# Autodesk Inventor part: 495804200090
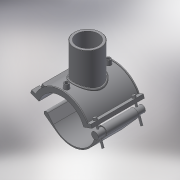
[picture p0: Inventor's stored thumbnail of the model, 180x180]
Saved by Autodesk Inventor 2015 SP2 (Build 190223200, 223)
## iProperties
Created: 2017-07
Part Number: 495804200090
Material: Generic
Description: PLASSON BRANCH SADDLE 200-90
Document SubType Name: Modeling
Designer: KIM
Density: 1 g/cm^3
Appearance: Default
Author: KIM
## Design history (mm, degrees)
derived "495804.ipt"
feature "Solid1::495804.ipt"
feature "Solid2::495804.ipt"
tag "TaggingFeature1"
body "Solid1"
body "Solid2"
other parameters: "d2" = 262.6, "d4" = 176, "d5" = 0, "d6" = 0.1, "d8" = 0, "d19" = 6, "d20" = 6, "d21" = 105.6, "d23" = 0, "d24" = 52.8, "d26" = 0, "d27" = 3, "d28" = 3, "d29" = 3, "d30" = 66.66667, "d31" = 6, "d32" = 0, "d33" = 0, "d34" = 0.6, "d40" = 119.6, "d41" = 99, "d43" = 0, "d45" = 0, "d50" = 0, "d70" = 15, "d72" = 0, "d73" = 6, "d75" = 5, "d76" = 0, "d79" = 15, "d80" = 70.4, "d82" = 5 deg, "d84" = 4, "d85" = 14, "d86" = 0, "d87" = 3, "d88" = 0, "d89" = 1, "d90" = 1, "d91" = 140.8, "d92" = 0, "d93" = 0.5, "d94" = 105.26316, "d96" = 234.6, "d97" = 3.52, "d98" = 0, "d102" = 2.7, "d103" = 72, "d105" = 0, "d109" = -35, "d117" = 0.9, "d120" = 140 deg, "d121" = 24.228, "d122" = 20 deg, "d124" = 138, "d126" = 0, "d150" = 36, "d159" = 6, "d161" = 5, "d162" = 105.6, "d163" = 0, "d168" = 104.54545, "d173" = 1, "d176" = 20 deg, "d177" = 14, "d180" = 0, "d185" = 57.2, "d186" = 57.2, "d187" = 115, "d188" = 9, "d189" = 14, "d190" = 0, "d191" = 172.5, "d200" = 15, "d202" = 0, "d216" = 158.4, "d217" = 0, "d221" = 65.12, "d222" = 14, "d223" = 8.4, "d225" = 8.4, "d227" = 28.8, "d230" = 124, "d236" = 20 deg, "d237" = 122, "d238" = 20 deg, "d239" = 14, "B_" = 202, "H_" = 105, "L_" = 176, "d_t" = 6, "d148" = 5, "d160" = 5
